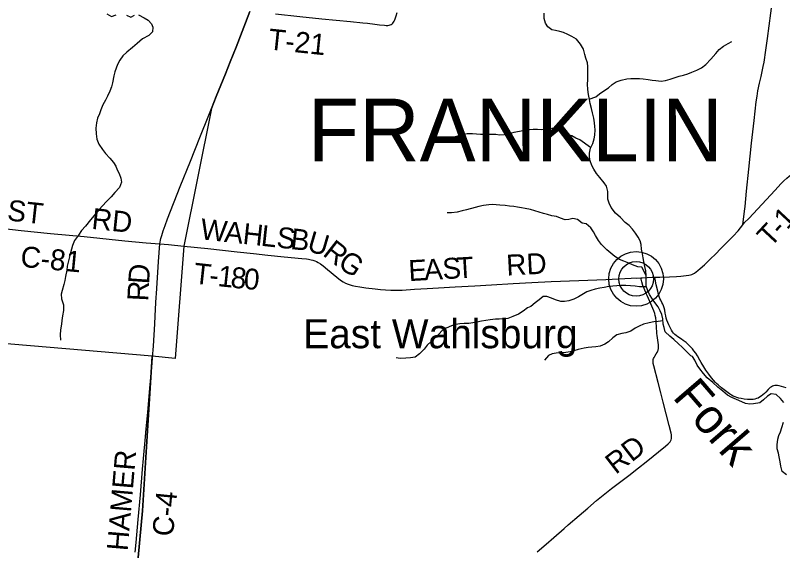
# Model space of a CAD drawing. Extents: x 1451455 to 1749751, y 218250 to 574981.
# Drawn here: x 1572855 to 1583864, y 330852 to 338538 of the extents above; entities that cross this region are included whole.
import ezdxf

# ---------------------------------------------------------------- set-up
doc = ezdxf.new("R2010")
doc.units = 0
for name, color, linetype in [('GM_X_County_Road', 7, 'Continuous'), ('GM_X_County_Road_Text', 7, 'Continuous'), ('GM_X_Minor_River', 7, 'Continuous'), ('GM_X_Minor_River_Text', 7, 'Continuous'), ('GM_X_Township', 7, 'Continuous'), ('GM_X_Township_Road', 7, 'Continuous'), ('GM_X_Township_Road_Text', 7, 'Continuous'), ('GM_X_Township_Text', 7, 'Continuous'), ('GM_X_Unincorporated', 7, 'Continuous'), ('GM_X_Unincorporated_Location', 7, 'Continuous'), ('GM_X_Unincorporated_Text', 7, 'Continuous')]:
    doc.layers.add(name, color=color, linetype=linetype)

msp = doc.modelspace()

# ---------------------------------------------------------------- linework, layer by layer
at = {"layer": 'GM_X_County_Road'}
for points in [[(1583294, 335531), (1583316, 335726), (1583325, 335794), (1583347, 336013), (1583379, 336329), (1583417, 336701), (1583455, 337030), (1583485, 337294), (1583497, 337375), (1583510, 337456), (1583533, 337562), (1583556, 337661), (1583586, 337802), (1583597, 337867), (1583622, 338036), (1583647, 338204), (1583694, 338569), (1583718, 338757), (1583733, 338861)], [(1575669, 337201), (1575737, 337370), (1575868, 337699), (1575937, 337869), (1576021, 338083), (1576221, 338593)], [(1574927, 335256), (1574944, 335334), (1574956, 335377), (1574976, 335444), (1575003, 335522), (1575038, 335614), (1575221, 336082), (1575366, 336444), (1575501, 336782), (1575630, 337102), (1575669, 337201)], [(1569297, 335835), (1569319, 335832), (1569341, 335830), (1569772, 335788), (1570382, 335721), (1570852, 335672), (1571293, 335627), (1571662, 335588), (1572066, 335545), (1572519, 335495), (1572937, 335447), (1573361, 335405), (1573841, 335360), (1574426, 335301), (1574733, 335271), (1574927, 335256)], [(1582031, 334777), (1582101, 334780), (1582242, 334785), (1582343, 334790), (1582402, 334795), (1582480, 334801), (1582517, 334806), (1582543, 334812), (1582562, 334818), (1582580, 334827), (1582601, 334838), (1582623, 334853), (1582649, 334873), (1582681, 334901), (1582742, 334957), (1582821, 335031), (1582910, 335118), (1582970, 335178), (1583154, 335366), (1583225, 335444), (1583294, 335531)], [(1574876, 334492), (1574879, 334539), (1574907, 335004), (1574927, 335256)], [(1580340, 330833), (1580471, 330947), (1580580, 331042), (1580728, 331171), (1580786, 331221), (1580945, 331357), (1581069, 331464), (1581194, 331571), (1581290, 331650), (1581409, 331743), (1581655, 331929), (1581797, 332040), (1581904, 332127), (1582182, 332352), (1582220, 332384), (1582237, 332401), (1582249, 332416), (1582259, 332431), (1582264, 332443), (1582269, 332460), (1582271, 332477), (1582271, 332493), (1582269, 332514), (1582264, 332540), (1582237, 332648), (1582150, 332985), (1582116, 333118), (1582078, 333264), (1582016, 333503), (1582008, 333537), (1582006, 333560), (1582006, 333579), (1582007, 333594), (1582012, 333609), (1582019, 333627), (1582030, 333646), (1582050, 333676), (1582064, 333699), (1582073, 333720), (1582076, 333730), (1582081, 333753), (1582082, 333777), (1582081, 333807), (1582078, 333839), (1582069, 333908), (1582064, 333943), (1582061, 333969), (1582058, 333998), (1582054, 334044), (1582052, 334083), (1582050, 334112), (1582047, 334148), (1582043, 334194), (1582037, 334227), (1582030, 334255), (1582018, 334293), (1582003, 334330), (1581974, 334396), (1581939, 334470), (1581919, 334515), (1581910, 334536), (1581877, 334614), (1581860, 334658), (1581843, 334710), (1581835, 334748), (1581831, 334768)], [(1581831, 334768), (1581849, 334769), (1581921, 334773), (1581990, 334776), (1582031, 334777)], [(1574823, 333623), (1574835, 333789), (1574854, 334110), (1574866, 334326), (1574876, 334492)], [(1574574, 330830), (1574586, 330969), (1574616, 331301), (1574648, 331654), (1574681, 332020), (1574695, 332174), (1574722, 332484), (1574727, 332546), (1574754, 332841), (1574786, 333184), (1574800, 333337), (1574817, 333543), (1574823, 333623)]]:
    msp.add_lwpolyline(points, dxfattribs=at)
at = {"layer": 'GM_X_Minor_River'}
for points in [[(1574167, 338557), (1574233, 338523), (1574301, 338546)], [(1574622, 338547), (1574701, 338502), (1574758, 338469), (1574806, 338418), (1574829, 338368), (1574824, 338301), (1574769, 338250), (1574678, 338198), (1574601, 338135)], [(1581908, 334802), (1581901, 334868), (1581886, 334931), (1581871, 335003), (1581864, 335055), (1581852, 335114), (1581841, 335182), (1581832, 335246), (1581819, 335300), (1581792, 335355), (1581755, 335409), (1581710, 335466), (1581660, 335519), (1581603, 335564), (1581538, 335633), (1581465, 335698), (1581406, 335781), (1581375, 335840), (1581358, 335900), (1581355, 335954), (1581356, 336006), (1581335, 336085), (1581303, 336135), (1581243, 336210), (1581195, 336269), (1581154, 336328), (1581125, 336380), (1581104, 336449), (1581095, 336501), (1581094, 336557), (1581107, 336629), (1581140, 336699), (1581158, 336763), (1581167, 336819), (1581172, 336893), (1581171, 336943), (1581166, 336993), (1581153, 337061), (1581134, 337140), (1581121, 337200), (1581104, 337270), (1581091, 337331), (1581080, 337399), (1581069, 337473), (1581064, 337548), (1581069, 337614), (1581071, 337802), (1581066, 337856), (1581041, 337921), (1581026, 337977), (1581005, 338053), (1580966, 338126), (1580907, 338195), (1580840, 338234), (1580784, 338261), (1580721, 338292), (1580665, 338307), (1580603, 338318), (1580551, 338330), (1580494, 338373), (1580461, 338426), (1580444, 338494), (1580443, 338571)], [(1574449, 338542), (1574511, 338511), (1574565, 338540)], [(1574601, 338135), (1574536, 338078), (1574455, 338011), (1574396, 337956), (1574355, 337896), (1574322, 337833), (1574301, 337779), (1574284, 337725), (1574269, 337669), (1574247, 337569), (1574234, 337513), (1574211, 337447), (1574178, 337378), (1574149, 337318), (1574112, 337251), (1574083, 337183), (1574060, 337123), (1574035, 337060), (1574020, 336996), (1574010, 336920), (1574013, 336835), (1574024, 336759), (1574051, 336686), (1574107, 336609), (1574147, 336555), (1574212, 336489), (1574265, 336424), (1574296, 336374), (1574317, 336319), (1574342, 336265), (1574367, 336198), (1574378, 336140), (1574351, 336066), (1574282, 335995), (1574231, 335934), (1574157, 335859), (1574108, 335808), (1574053, 335743), (1574010, 335691), (1573935, 335602), (1573859, 335513), (1573802, 335448), (1573759, 335381), (1573702, 335305), (1573673, 335232), (1573658, 335178), (1573639, 335108), (1573619, 335014), (1573600, 334934), (1573591, 334880), (1573574, 334790), (1573565, 334732), (1573552, 334674), (1573526, 334589), (1573511, 334533), (1573518, 334467), (1573545, 334380), (1573544, 334302), (1573532, 334222), (1573523, 334156), (1573516, 334102), (1573503, 334020), (1573500, 333952), (1573501, 333874)], [(1581090, 337333), (1581183, 337367), (1581236, 337409), (1581300, 337456), (1581363, 337499), (1581419, 337544), (1581474, 337582), (1581548, 337607), (1581628, 337626), (1581684, 337633), (1581808, 337631), (1581864, 337626), (1581934, 337617), (1581994, 337608), (1582046, 337600), (1582122, 337594), (1582182, 337600), (1582252, 337621), (1582308, 337640), (1582380, 337663), (1582440, 337680), (1582503, 337699), (1582563, 337720), (1582635, 337751), (1582702, 337783), (1582760, 337832), (1582833, 337909), (1582905, 337990), (1582953, 338048), (1583016, 338095), (1583084, 338134), (1583137, 338163)], [(1581112, 336641), (1581091, 336651), (1581022, 336702), (1580952, 336748), (1580899, 336776), (1580839, 336807), (1580772, 336826), (1580706, 336871), (1580635, 336910), (1580581, 336917), (1580519, 336910), (1580463, 336897), (1580407, 336894), (1580345, 336897), (1580285, 336897), (1580233, 336896), (1580159, 336885), (1580087, 336872), (1580005, 336855), (1579941, 336838), (1579866, 336823), (1579802, 336818), (1579747, 336825), (1579685, 336828), (1579609, 336829), (1579531, 336826), (1579471, 336831), (1579413, 336836), (1579337, 336837), (1579265, 336824), (1579211, 336809), (1579138, 336784), (1579066, 336769), (1578995, 336782), (1578943, 336780)], [(1581908, 334802), (1581844, 334921), (1581788, 334926), (1581710, 334957), (1581655, 334980), (1581585, 335009), (1581524, 335034), (1581458, 335077), (1581340, 335169), (1581265, 335246), (1581222, 335305), (1581179, 335376), (1581148, 335430), (1581114, 335487), (1581047, 335544), (1580989, 335555), (1580920, 335608), (1580852, 335619), (1580798, 335604), (1580746, 335602), (1580677, 335627), (1580617, 335648), (1580553, 335661), (1580490, 335676), (1580432, 335693), (1580309, 335731), (1580245, 335750), (1580171, 335765), (1580115, 335774), (1580059, 335782), (1580006, 335791), (1579946, 335800), (1579884, 335805), (1579806, 335814), (1579754, 335819), (1579702, 335820), (1579646, 335818), (1579574, 335807), (1579506, 335794), (1579452, 335779), (1579326, 335745), (1579265, 335730), (1579193, 335713), (1579111, 335700), (1579049, 335701)], [(1583879, 332980), (1583831, 333035), (1583772, 333094), (1583698, 333101), (1583648, 333070), (1583587, 333019), (1583537, 332973), (1583445, 332961), (1583395, 332955), (1583331, 332966), (1583279, 332987), (1583204, 333022), (1583134, 333051), (1583075, 333082), (1583004, 333143), (1582932, 333198), (1582861, 333266), (1582783, 333335), (1582727, 333396), (1582676, 333461), (1582637, 333513), (1582604, 333586), (1582569, 333640), (1582549, 333651), (1582490, 333704), (1582421, 333775), (1582370, 333820), (1582301, 333885), (1582245, 333930), (1582180, 333995), (1582163, 334055), (1582152, 334105), (1582145, 334178), (1582132, 334242), (1582109, 334296), (1582077, 334353), (1582030, 334414), (1581999, 334464), (1581954, 334531), (1581925, 334597), (1581908, 334650), (1581907, 334720), (1581908, 334802)], [(1581911, 334639), (1581880, 334638), (1581812, 334641), (1581746, 334648), (1581682, 334653), (1581612, 334658), (1581548, 334659), (1581484, 334656), (1581426, 334649), (1581370, 334642), (1581304, 334632), (1581240, 334621), (1581172, 334604), (1581114, 334589), (1581053, 334568), (1580983, 334527), (1580933, 334498), (1580868, 334462), (1580796, 334437), (1580736, 334428), (1580682, 334431), (1580604, 334452), (1580549, 334475), (1580481, 334502), (1580427, 334503), (1580372, 334455), (1580314, 334412), (1580251, 334357), (1580201, 334336), (1580140, 334290), (1580074, 334249), (1579995, 334214), (1579919, 334187), (1579863, 334178), (1579797, 334175), (1579745, 334174), (1579669, 334165), (1579607, 334156), (1579541, 334147), (1579477, 334132), (1579417, 334121), (1579361, 334115), (1579293, 334112), (1579231, 334107), (1579174, 334098), (1579112, 334081), (1579034, 334048), (1578981, 334015), (1578933, 333961), (1578876, 333912), (1578819, 333855), (1578765, 333803), (1578720, 333746), (1578653, 333677), (1578592, 333631), (1578526, 333618), (1578456, 333613), (1578374, 333610), (1578318, 333619)], [(1582147, 334152), (1582079, 334142), (1582014, 334135), (1581950, 334124), (1581868, 334103), (1581806, 334074), (1581749, 334047), (1581685, 334004), (1581615, 333981), (1581555, 333968), (1581486, 333949), (1581426, 333909), (1581365, 333850), (1581315, 333815), (1581248, 333790), (1581186, 333779), (1581128, 333775), (1581074, 333768), (1581016, 333759), (1580932, 333738), (1580868, 333721), (1580815, 333708), (1580751, 333697), (1580675, 333694), (1580615, 333689), (1580559, 333677), (1580505, 333652), (1580446, 333585)], [(1583920, 331940), (1583859, 331989), (1583836, 332065), (1583829, 332126), (1583814, 332200), (1583804, 332252), (1583787, 332315), (1583784, 332371), (1583793, 332451), (1583808, 332503), (1583831, 332558), (1583852, 332618), (1583875, 332696)]]:
    msp.add_lwpolyline(points, dxfattribs=at)
at = {"layer": 'GM_X_Township'}
for points in [[(1576221, 338593), (1576021, 338083), (1575937, 337869), (1575868, 337699), (1575737, 337370), (1575669, 337201), (1575273, 335223), (1575149, 333612), (1574820, 333643), (1569350, 334108)], [(1576221, 338593), (1576021, 338083), (1575937, 337869), (1575868, 337699), (1575737, 337370), (1575669, 337201), (1575273, 335223), (1575149, 333612), (1574820, 333643), (1574681, 331422), (1574496, 329466), (1574442, 328971), (1576082, 328034), (1576825, 327623), (1581501, 324963)], [(1581501, 324963), (1576825, 327623), (1576082, 328034), (1574442, 328971), (1574496, 329466), (1574681, 331422), (1574820, 333643), (1569350, 334108)]]:
    msp.add_lwpolyline(points, dxfattribs=at)
at = {"layer": 'GM_X_Township_Road'}
for points in [[(1576586, 338560), (1576935, 338522), (1577252, 338489), (1577663, 338449), (1577840, 338431), (1577908, 338424), (1578012, 338412), (1578080, 338403), (1578149, 338395), (1578174, 338393), (1578200, 338393), (1578219, 338395), (1578234, 338399), (1578248, 338406), (1578260, 338415), (1578271, 338426), (1578281, 338439), (1578290, 338455), (1578298, 338473), (1578310, 338503), (1578318, 338531), (1578333, 338578)], [(1583294, 335531), (1583319, 335562), (1583378, 335623), (1583756, 336029), (1583839, 336117), (1583883, 336161), (1583924, 336199), (1583959, 336229), (1583995, 336257), (1584040, 336290), (1584083, 336320), (1584138, 336356), (1584204, 336398), (1584258, 336429), (1584313, 336461), (1584372, 336495), (1584452, 336540), (1584518, 336576), (1584558, 336598)], [(1574927, 335256), (1575054, 335245), (1575273, 335223)], [(1575273, 335223), (1575618, 335188), (1576036, 335143), (1576271, 335118), (1576479, 335096), (1576711, 335072), (1576963, 335048), (1577031, 335041), (1577060, 335037), (1577079, 335034), (1577101, 335029), (1577123, 335023), (1577154, 335012), (1577174, 335003), (1577200, 334989), (1577233, 334968), (1577272, 334939), (1577333, 334889), (1577467, 334778), (1577519, 334737), (1577557, 334711), (1577592, 334692), (1577628, 334676), (1577657, 334667), (1577689, 334658), (1577734, 334649), (1577796, 334639), (1577883, 334626), (1578017, 334609), (1578092, 334601), (1578164, 334595), (1578240, 334592), (1578322, 334592), (1578407, 334594), (1578584, 334604), (1578764, 334615), (1578928, 334624), (1579164, 334639), (1579449, 334655), (1579685, 334668), (1579996, 334687), (1580264, 334701), (1580543, 334714), (1580942, 334731), (1581329, 334747), (1581689, 334762), (1581831, 334768)], [(1583916, 333189), (1583850, 333210), (1583815, 333220), (1583792, 333224), (1583770, 333225), (1583751, 333223), (1583735, 333220), (1583720, 333214), (1583702, 333206), (1583686, 333194), (1583674, 333184), (1583658, 333167), (1583621, 333125), (1583603, 333107), (1583580, 333087), (1583557, 333070), (1583532, 333054), (1583511, 333043), (1583487, 333034), (1583465, 333027), (1583443, 333023), (1583423, 333021), (1583400, 333020), (1583358, 333023), (1583313, 333029), (1583270, 333036), (1583235, 333042), (1583209, 333049), (1583182, 333059), (1583155, 333071), (1583129, 333085), (1583101, 333103), (1583064, 333130), (1582987, 333191), (1582939, 333231), (1582915, 333252), (1582901, 333266), (1582871, 333300), (1582844, 333333), (1582805, 333386), (1582764, 333445), (1582733, 333492), (1582696, 333554), (1582677, 333588), (1582642, 333647), (1582617, 333686), (1582592, 333721), (1582569, 333749), (1582543, 333778), (1582510, 333810), (1582478, 333838), (1582439, 333869), (1582412, 333887), (1582360, 333921), (1582336, 333939), (1582317, 333956), (1582299, 333975), (1582285, 333994), (1582271, 334016), (1582231, 334095), (1582216, 334127), (1582203, 334160), (1582194, 334189), (1582186, 334221), (1582179, 334260), (1582172, 334304), (1582164, 334340), (1582155, 334368), (1582145, 334392), (1582133, 334416), (1582116, 334447), (1582103, 334474), (1582094, 334499), (1582084, 334530), (1582072, 334578), (1582051, 334670), (1582036, 334748), (1582031, 334777)]]:
    msp.add_lwpolyline(points, dxfattribs=at)
at = {"layer": 'GM_X_Unincorporated'}
for radius in [393, 249]:
    msp.add_circle((1581761, 334753), radius, dxfattribs=at)
at = {"layer": 'GM_X_Unincorporated_Location'}
msp.add_line((1581761, 334753), (1581761, 334753), dxfattribs=at)

# ---------------------------------------------------------------- texts
at = {"layer": 'GM_X_County_Road_Text'}
for s, rotation, p in [('EAST', 353.7147, (1572196, 335653)), ('RD', 354.0943, (1573940, 335473)), ('C-81', 354.5277, (1572919, 334929)), ('D', 86.0955, (1574772, 334672)), ('R', 87.138, (1574760, 334428)), ('RD', 37.7111, (1581468, 331938)), ('HAMER', 85.0795, (1574465, 330840)), ('C-4', 84.5139, (1575116, 331047))]:
    msp.add_text(s, height=300, rotation=rotation, dxfattribs=at).set_placement(p)
at = {"layer": 'GM_X_Minor_River_Text'}
msp.add_text('Fork', height=500.1, rotation=310.7807, dxfattribs=at).set_placement((1582272, 333051))
at = {"layer": 'GM_X_Township_Road_Text'}
for s, rotation, p in [('T-21', 354.0094, (1576473, 338050)), ('1', 46.9691, (1583927, 335449)), ('W', 353.8518, (1575499, 335324)), ('A', 353.8516, (1575844, 335286)), ('H', 353.8516, (1576107, 335258)), ('L', 353.8517, (1576369, 335230)), ('S', 353.8512, (1576592, 335206)), ('B', 353.5523, (1576793, 335184)), ('T', 47.0687, (1583690, 335195)), ('-', 47.0455, (1583843, 335359)), ('U', 343.7491, (1577025, 335159)), ('R', 322.029, (1577251, 335099)), ('G', 326.2393, (1577465, 334933)), ('E', 3.2073, (1578503, 334721)), ('A', 3.2086, (1578727, 334734)), ('S', 3.209, (1578990, 334749)), ('T', 3.3552, (1579193, 334760)), ('RD', 2.9612, (1579906, 334800)), ('T', 353.7973, (1575403, 334688)), ('1', 353.8526, (1575749, 334651)), ('8', 354.034, (1575934, 334631)), ('0', 354.8904, (1576123, 334611)), ('-', 353.8156, (1575626, 334664))]:
    msp.add_text(s, height=300, rotation=rotation, dxfattribs=at).set_placement(p)
at = {"layer": 'GM_X_Township_Text'}
msp.add_text('FRANKLIN', height=900, rotation=0, dxfattribs=at).set_placement((1577052, 336440))
at = {"layer": 'GM_X_Unincorporated_Text'}
msp.add_text('East Wahlsburg', height=417, rotation=0, dxfattribs=at).set_placement((1576986, 333758))

doc.saveas('drawing.dxf')
